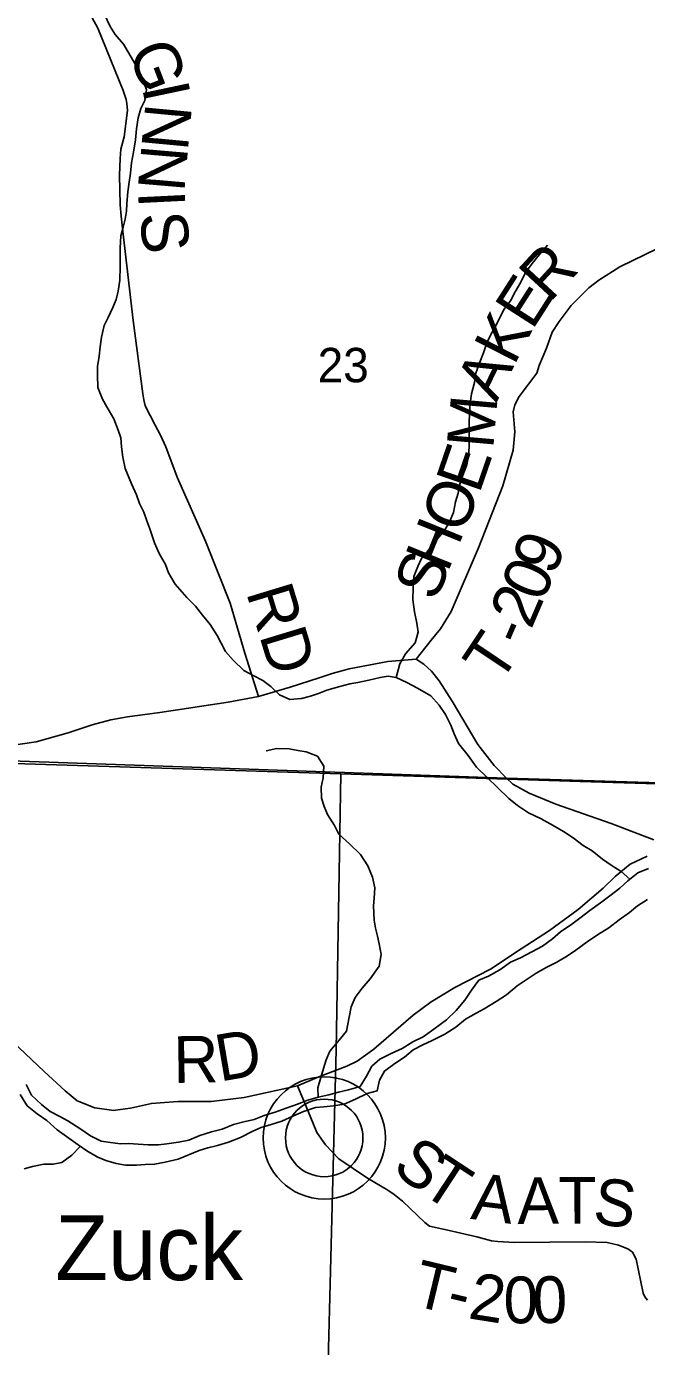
# Model space of a CAD drawing. Extents: x 1759416 to 2214760, y 252598 to 1116833.
# Drawn here: x 2040039 to 2044026, y 864951 to 873433 of the extents above; entities that cross this region are included whole.
import ezdxf

# ---------------------------------------------------------------- set-up
doc = ezdxf.new("R2010")
doc.units = 0
for name, color, linetype in [('GM_X_Major_River', 7, 'Continuous'), ('GM_X_Minor_Lake', 7, 'Continuous'), ('GM_X_Minor_River', 7, 'Continuous'), ('GM_X_Section', 7, 'Continuous'), ('GM_X_Section_Text', 7, 'Continuous'), ('GM_X_State_Route', 7, 'Continuous'), ('GM_X_Township', 7, 'Continuous'), ('GM_X_Township_Road', 7, 'Continuous'), ('GM_X_Township_Road_Text', 7, 'Continuous'), ('GM_X_Unincorporated', 7, 'Continuous'), ('GM_X_Unincorporated_Location', 7, 'Continuous'), ('GM_X_Unincorporated_Text', 7, 'Continuous')]:
    doc.layers.add(name, color=color, linetype=linetype)

msp = doc.modelspace()

# ---------------------------------------------------------------- linework, layer by layer
at = {"layer": 'GM_X_Major_River'}
for points in [[(2044036.7, 868021.9), (2043968.9, 867995.6), (2043905.1, 867943.3), (2043853.2, 867897.1), (2043789.4, 867846.8), (2043729.6, 867802.5), (2043659.8, 867752.3), (2043596, 867704), (2043544.1, 867665.8), (2043472.3, 867615.4), (2043420.5, 867571.2), (2043356.7, 867522.9), (2043286.9, 867486.7), (2043215, 867448.4), (2043151.1, 867420.1), (2043081.4, 867371.8), (2043009.5, 867331.5), (2042947.6, 867305.3), (2042899.9, 867241), (2042858.1, 867176.8), (2042802.3, 867110.6), (2042738.6, 867050.3), (2042656.8, 866989.9), (2042589, 866941.6), (2042523.1, 866909.4), (2042453.3, 866867.1), (2042383.4, 866834.8), (2042311.6, 866798.5), (2042259.8, 866752.3), (2042224, 866688.1), (2042184.2, 866621.9), (2042108.3, 866599.6), (2042044.4, 866585.3), (2041982.5, 866569.1), (2041914.6, 866552.8), (2041848.7, 866534.6), (2041780.8, 866508.3), (2041709, 866482), (2041637.1, 866457.7), (2041567.2, 866435.5), (2041503.3, 866409.2), (2041437.4, 866395), (2041369.5, 866378.7), (2041297.6, 866348.4), (2041229.7, 866330.2), (2041153.9, 866307.9), (2041084, 866277.6), (2041016.1, 866263.3), (2040942.2, 866253), (2040888.2, 866246.8), (2040822.3, 866246.6), (2040758.3, 866252.4), (2040698.3, 866256.2), (2040644.4, 866254), (2040578.4, 866261.7), (2040518.4, 866271.5), (2040450.3, 866305.3), (2040382.2, 866353.1), (2040306.1, 866400.9), (2040254.1, 866428.7), (2040192, 866460.5), (2040135.9, 866506.3), (2040071.8, 866566.2), (2040037.6, 866634.1)], [(2039999.8, 866569.9), (2040044, 866498), (2040108.1, 866446.2), (2040170.2, 866404.4), (2040236.4, 866342.6), (2040296.4, 866300.7), (2040370.6, 866247), (2040434.6, 866205.2), (2040498.7, 866167.3), (2040548.8, 866147.5), (2040614.8, 866127.7), (2040676.8, 866115.9), (2040746.7, 866116.2), (2040802.7, 866120.4), (2040862.6, 866122.6), (2040930.5, 866134.9), (2041014.4, 866155.2), (2041150.2, 866211.8), (2041204.1, 866228), (2041268, 866242.2), (2041337.9, 866264.5), (2041415.7, 866294.8), (2041493.6, 866335.1), (2041547.4, 866359.3), (2041611.3, 866377.6), (2041681.2, 866399.8), (2041751.1, 866432.1), (2041819, 866460.4), (2041896.8, 866486.7), (2041950.8, 866490.9), (2042012.7, 866497.1), (2042080.6, 866509.4), (2042154.5, 866539.7), (2042228.3, 866576), (2042294.2, 866594.2), (2042308, 866662.4), (2042339.8, 866720.5), (2042407.6, 866768.8), (2042469.5, 866811.1), (2042525.3, 866857.3), (2042587.1, 866889.6), (2042647, 866917.8), (2042728.8, 866958.2), (2042798.7, 867002.4), (2042860.5, 867054.7), (2042930.3, 867093), (2042982.2, 867121.2), (2043058, 867167.5), (2043125.8, 867211.8), (2043193.6, 867268.1), (2043263.4, 867316.4), (2043315.3, 867350.6), (2043385.1, 867388.9), (2043449, 867421.2), (2043516.8, 867461.5), (2043570.6, 867497.7), (2043644.4, 867552), (2043710.3, 867596.3), (2043782.1, 867640.6), (2043849.9, 867692.9), (2043915.7, 867739.2), (2043967.5, 867783.4), (2044031.3, 867823.7)]]:
    msp.add_lwpolyline(points, dxfattribs=at)
at = {"layer": 'GM_X_Minor_Lake'}
msp.add_lwpolyline([(2040385.2, 866237.4), (2040331.8, 866181.2), (2040265.8, 866133.1), (2040211.8, 866123.1), (2040151.9, 866123.1), (2040077.9, 866109), (2040023.9, 866093)], dxfattribs=at)
at = {"layer": 'GM_X_Minor_River'}
for points in [[(2040751.5, 873169.4), (2040697.5, 873261.5), (2040663.5, 873319.6), (2040609.6, 873381.7), (2040577.6, 873431.7), (2040541.6, 873509.8), (2040521.6, 873565.9), (2040501.7, 873632), (2040495.7, 873684.1)], [(2043917.6, 867953.5), (2043861, 868003.1), (2043797.1, 868045.1), (2043741.1, 868083.1), (2043675.1, 868137.2), (2043617.2, 868171.2), (2043553.2, 868219.3), (2043491.2, 868261.3), (2043425.3, 868299.3), (2043347.3, 868341.4), (2043267.3, 868379.4), (2043195.4, 868427.4), (2043139.4, 868473.5), (2043067.5, 868543.6), (2043001.5, 868607.6), (2042931.5, 868673.7), (2042879.6, 868747.8), (2042815.6, 868825.9), (2042789.6, 868888), (2042767.7, 868944), (2042733.7, 869012.1), (2042691.7, 869072.2), (2042637.8, 869132.3), (2042553.8, 869180.3), (2042483.8, 869218.3), (2042415.9, 869250.4), (2042363.9, 869258.3), (2042311.9, 869250.3), (2042239.9, 869232.3), (2042169.9, 869218.2), (2042118, 869208.2), (2042054, 869192.2), (2041970, 869168.1), (2041916, 869148), (2041864, 869130), (2041808, 869113.9), (2041732.1, 869107.9), (2041666.1, 869137.9), (2041610.1, 869192), (2041558.2, 869230), (2041500.2, 869260.1), (2041436.2, 869294.1), (2041368.3, 869360.2), (2041318.3, 869416.2), (2041290.3, 869470.3), (2041264.3, 869520.3), (2041220.4, 869590.4), (2041170.4, 869650.5), (2041126.4, 869708.6), (2041070.5, 869764.6), (2040994.5, 869848.7), (2040952.6, 869922.8), (2040932.6, 869976.9), (2040892.6, 870047), (2040862.6, 870115.1), (2040832.7, 870205.2), (2040812.7, 870257.2), (2040794.7, 870311.3), (2040766.7, 870367.4), (2040746.7, 870423.5), (2040714.8, 870493.6), (2040672.8, 870593.7), (2040658.8, 870665.8), (2040650.9, 870731.9), (2040644.9, 870789.9), (2040628.9, 870840), (2040600.9, 870912.1), (2040555, 870988.2), (2040527, 871038.3), (2040499, 871112.4), (2040495, 871192.5), (2040495, 871248.6), (2040507.1, 871314.7), (2040513.1, 871374.8), (2040521.1, 871436.8), (2040539.1, 871510.9), (2040565.1, 871563), (2040595.1, 871627.1), (2040615.1, 871679.2), (2040629.1, 871731.3), (2040639.1, 871803.4), (2040641.2, 871887.5), (2040641.2, 872007.7), (2040645.2, 872087.8), (2040661.2, 872143.9), (2040673.2, 872194), (2040683.2, 872246.1), (2040685.3, 872296.1), (2040691.3, 872370.2), (2040699.3, 872432.3), (2040707.3, 872490.4), (2040715.3, 872556.5), (2040727.3, 872624.6), (2040739.3, 872704.7), (2040747.4, 872774.8), (2040757.4, 872844.9), (2040773.4, 872905), (2040799.4, 872957.1), (2040811.4, 873025.2), (2040779.4, 873115.3), (2040751.5, 873169.4)], [(2042415.9, 869250.4), (2042439.9, 869338.5), (2042475.9, 869402.6), (2042537.9, 869472.7), (2042557.9, 869540.8), (2042547.9, 869598.9), (2042533.9, 869671), (2042522, 869751.1), (2042524, 869825.2), (2042530, 869899.3), (2042556, 869963.4), (2042578, 870015.5), (2042632, 870079.6), (2042678, 870135.7), (2042726, 870193.8), (2042760, 870253.9), (2042784, 870310), (2042798, 870378.1), (2042814, 870434.2), (2042826, 870492.3), (2042844.1, 870550.4), (2042870.1, 870616.5), (2042882.1, 870684.6), (2042884.1, 870750.7), (2042884.1, 870888.9), (2042888.1, 870942.9), (2042892.2, 871011), (2042900.2, 871073.1), (2042918.2, 871145.2), (2042928.2, 871205.3), (2042950.2, 871265.4), (2042976.2, 871335.5), (2042998.2, 871399.6), (2043024.2, 871453.7), (2043060.2, 871517.8), (2043108.2, 871614), (2043150.2, 871670.1), (2043180.2, 871728.2), (2043216.3, 871790.3), (2043246.3, 871852.4), (2043290.3, 871910.5), (2043336.3, 871968.6), (2043388.3, 872026.7)], [(2041914.6, 866552.8), (2041911.4, 866614.4), (2041931.4, 866680.5), (2041949.4, 866738.6), (2041965.4, 866792.7), (2041989.4, 866848.8), (2042049.4, 866918.9), (2042097.4, 866977), (2042113.4, 867067.1), (2042127.4, 867133.2), (2042151.4, 867193.3), (2042197.4, 867253.4), (2042249.4, 867313.5), (2042307.4, 867395.7), (2042319.4, 867469.8), (2042307.5, 867537.9), (2042295.5, 867587.9), (2042283.5, 867640), (2042273.5, 867690.1), (2042269.5, 867782.2), (2042273.6, 867832.3), (2042279.6, 867898.4), (2042263.6, 867966.5), (2042233.6, 868040.6), (2042185.7, 868112.7), (2042115.7, 868180.7), (2042047.7, 868242.8), (2042019.8, 868298.9), (2041973.8, 868368.9), (2041953.8, 868421), (2041935.8, 868475.1), (2041933.8, 868545.2), (2041945.9, 868605.3), (2041949.9, 868679.4), (2041909.9, 868745.5), (2041837.9, 868771.5), (2041784, 868781.5), (2041728, 868791.5), (2041648, 868793.4), (2041580, 868779.4)]]:
    msp.add_lwpolyline(points, dxfattribs=at)
at = {"layer": 'GM_X_Section'}
for points in [[(2039339.4, 874074.5), (2044848, 873945.7), (2044729, 868547.3), (2043598, 868582.4), (2042059.6, 868630.1), (2039418.3, 868714.9)], [(2039418.3, 868714.9), (2042059.6, 868630.1), (2042029.7, 866857.3), (2041943.1, 863435.9), (2038607.6, 863518.2), (2038714, 868730.4)]]:
    msp.add_lwpolyline(points, close=True, dxfattribs=at)
at = {"layer": 'GM_X_State_Route'}
msp.add_lwpolyline([(2039805.9, 868793.8), (2040100.6, 868836.7), (2040308.2, 868893.8), (2040462.5, 868945.3), (2040582.5, 868977.7), (2040689.2, 868996.7), (2040896.8, 869025.3), (2041336.8, 869092), (2041531.1, 869128.2), (2041734.7, 869188.7), (2041919.7, 869248.2), (2042003.5, 869276.5), (2042114.2, 869304.9), (2042362.7, 869352.2), (2042545, 869368.4), (2042593.7, 869334.6), (2042642.3, 869290), (2042692.3, 869229.2), (2042774.7, 869098.2), (2042940.8, 868819.9), (2043046.3, 868683.8), (2043125.1, 868603), (2043165.4, 868564.6), (2043270.9, 868506.7), (2043441.1, 868436.8), (2043798.7, 868311), (2044071.8, 868206.7)], dxfattribs=at)
at = {"layer": 'GM_X_Township'}
for points in [[(2045938.1, 868518), (2043125.1, 868603), (2039321, 868736.1), (2039114.7, 868742.5), (2038695.2, 868755.1), (2038542, 868757.7), (2038303.5, 868739.2), (2038187.2, 868731.8), (2036756.4, 868762.3), (2032951, 868877.9), (2029619.2, 869035.3), (2029373.3, 869044.9), (2029381.6, 869128.9), (2029454.2, 872116.1), (2029477.2, 872874.6), (2029517.7, 874723), (2029528, 876297.5), (2029509.2, 876366), (2029514, 876470.8), (2029512.1, 877091.5), (2029569.5, 879745.3), (2029620.6, 882518), (2029741.2, 887327.4)], [(2029127.9, 855176.9), (2029344.8, 867782.7), (2029361.5, 867821.8), (2029373.3, 869044.9), (2029619.2, 869035.3), (2032951, 868877.9), (2036756.4, 868762.3), (2038187.2, 868731.8), (2038303.5, 868739.2), (2038542, 868757.7), (2038695.2, 868755.1), (2039114.7, 868742.5), (2039321, 868736.1), (2043125.1, 868603), (2045938.1, 868518), (2052378.5, 868323.3), (2053775, 868281.1), (2055375.9, 868232.8), (2055264.7, 865387.8), (2055261.6, 865247.5), (2054985.8, 859394.5), (2054896.4, 855719.9)]]:
    msp.add_lwpolyline(points, dxfattribs=at)
at = {"layer": 'GM_X_Township_Road'}
for points in [[(2040460.8, 873487.6), (2040497.2, 873422.6), (2040661.3, 873022.3), (2040679.9, 872963.8), (2040685.3, 872937.7), (2040688.2, 872893.5), (2040668.2, 872723.8), (2040646.3, 872644.2), (2040640.9, 872584.3), (2040636.3, 872478.2), (2040641.8, 872285.9), (2040648, 872213.7), (2040661.2, 872099.2), (2040725.8, 871543.1), (2040786.5, 871073.1), (2040793.5, 871034.9), (2040802.5, 870994.6), (2040867.5, 870871), (2040899.9, 870806.1), (2040936, 870731.2), (2041007.3, 870537.3), (2041189.2, 870126.6), (2041348.2, 869728.4), (2041443.5, 869406.4), (2041531.1, 869128.2)], [(2042545, 869368.4), (2042641, 869490), (2042701.7, 869562.9), (2042769.2, 869673.7), (2042944.1, 870083.2), (2043100.7, 870481.5), (2043168.8, 870709.6), (2043179, 870828.8), (2043167.8, 870957.1), (2043178.9, 871000.9), (2043206.1, 871054.3), (2043319.6, 871205.8), (2043334.7, 871255.5), (2043381.3, 871366.6), (2043417.7, 871467.8), (2043463.3, 871536.9), (2043539.6, 871639.2), (2043654.1, 871752.7), (2043719.2, 871803.2), (2043853, 871888.2), (2044174.3, 872044.8)], [(2038695.2, 868755.2), (2038713.4, 868699), (2038711.6, 868612.5), (2038702.4, 868237.1), (2038696.1, 867826.3), (2038697, 867786.7), (2038716.3, 867739.4), (2038761.6, 867667.6), (2038939.4, 867497.9), (2039055.5, 867431.4), (2039198.3, 867368.3), (2039467.1, 867252.1), (2039686.7, 867147.5), (2039764.8, 867087), (2039865.6, 866988.8), (2039991.5, 866870.3), (2040153.6, 866718.7), (2040287.1, 866593.3), (2040365.3, 866529.8), (2040479.3, 866485.8), (2040601.5, 866467.9), (2040610.8, 866469.1)], [(2040610.8, 866469.1), (2040707.3, 866482.5), (2040842.5, 866513.5), (2040927.2, 866520), (2041015.1, 866526.5), (2041226.8, 866524.9), (2041438.5, 866550.9), (2041782.4, 866626.5), (2041919.5, 866683.4), (2042098.9, 866753.2), (2042165.6, 866785.7), (2042271.2, 866861.3), (2042526, 867079.6), (2042639.9, 867165), (2042791.8, 867257.6), (2043022.3, 867376.3), (2043219.6, 867505.6), (2043401.5, 867625.3), (2043584.6, 867759.6), (2043745.6, 867896), (2043823.3, 867972.2), (2043918.9, 868050.2), (2044029.4, 868100.9)], [(2041782.4, 866626.5), (2041837.1, 866493.1), (2041882.4, 866383.9), (2041905, 866327.3), (2041961, 866247.9), (2042046.7, 866157.8), (2042231.4, 866033.3), (2042361.4, 865956.1), (2042402.7, 865929.1), (2042455.6, 865885.9), (2042553.2, 865793.4), (2042600, 865748.3), (2042629.4, 865725.6), (2042728.7, 865703.3), (2042933.3, 865656.4), (2043028.5, 865630.1), (2043068.3, 865625.2), (2043174, 865620.7), (2043633.4, 865623.9), (2043773, 865618.6), (2043844.5, 865603), (2043903.9, 865579.5), (2043935.3, 865556.8), (2043958.2, 865512.2), (2044002.9, 865294.9), (2044014.3, 865270.6), (2044031.7, 865248.1)]]:
    msp.add_lwpolyline(points, dxfattribs=at)
at = {"layer": 'GM_X_Unincorporated'}
for radius in [392.8, 249]:
    msp.add_circle((2041953.5, 866291.5), radius, dxfattribs=at)
at = {"layer": 'GM_X_Unincorporated_Location'}
msp.add_line((2041953.5, 866291.5), (2041953.5, 866291.5), dxfattribs=at)

# ---------------------------------------------------------------- texts
at = {"layer": 'GM_X_Section_Text'}
msp.add_text('23', height=221, rotation=0.00001, dxfattribs=at).set_placement((2041910.8, 871146.8))
at = {"layer": 'GM_X_Township_Road_Text'}
for s, rotation, p in [('G', 291.06001, (2040689.4, 873276.2)), ('I', 281.91922, (2040780.6, 873041.9)), ('N', 264.59351, (2040804.7, 872945.2)), ('N', 265.10311, (2040779.6, 872679.5)), ('I', 272.81924, (2040756.2, 872372.4)), ('S', 276.8705, (2040764.2, 872226.2)), ('R', 47.23325, (2043402.5, 871654.2)), ('E', 57.35592, (2043290, 871476.3)), ('K', 62.88921, (2043173.5, 871247.9)), ('A', 64.31958, (2043060, 871011.8)), ('M', 85.02102, (2043039.3, 870714.9)), ('E', 70.97488, (2042949.5, 870424.4)), ('O', 68.16027, (2042845.6, 870164.3)), ('H', 68.03203, (2042746.6, 869918.8)), ('9', 67.39588, (2043428.3, 869896.7)), ('S', 68.02742, (2042670.8, 869731)), ('0', 67.27062, (2043356.6, 869725.6)), ('RD', 286.92706, (2041449.9, 869797.8)), ('2', 66.79068, (2043282.7, 869553.3)), ('T', 56.18631, (2043080, 869200.7)), ('-', 66.57072, (2043233.3, 869439.1)), ('R', 0.87822, (2040985.8, 866644.6)), ('D', 9.70862, (2041281.6, 866652.9)), ('S', 322.16461, (2042380.6, 866085.5)), ('T', 326.71267, (2042561.6, 865946.2)), ('A', 353.04841, (2042889.4, 865771.7)), ('A', 0.74724, (2043195.3, 865737.4)), ('T', 0.04285, (2043458.3, 865740.8)), ('S', 353.10364, (2043673.1, 865741.6)), ('T', 346.42526, (2042507.9, 865219.6)), ('2', 351.05287, (2042871.8, 865133.3)), ('0', 0.1099, (2043105.8, 865100.6)), ('0', 0.67181, (2043293.8, 865101)), ('-', 346.66048, (2042727.3, 865166.6))]:
    msp.add_text(s, height=300, rotation=rotation, dxfattribs=at).set_placement(p)
at = {"layer": 'GM_X_Unincorporated_Text'}
msp.add_text('Zuck', height=417, rotation=0.00001, dxfattribs=at).set_placement((2040223.4, 865377.8))

doc.saveas('drawing.dxf')
